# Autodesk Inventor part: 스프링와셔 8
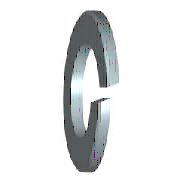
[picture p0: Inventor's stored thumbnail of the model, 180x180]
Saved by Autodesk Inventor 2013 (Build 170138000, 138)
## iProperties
IsCustomPart: 1
Created: 2012-02
Part Number: 스프링와셔 8
Material: 강철, 연강
Description: 스프링 잠금 와셔
Document SubType Name: Modeling
Standard: KS B 1324
Designer: mduedu
Standards Organization: KS
Language: ko-KR
Size Designation: 번호 3 - 8
Categories: <MemberInstance><Categories><Category DisplayName="조임쇠" InternalName="e4da775c-781d-43d5-af7c-5136215cf5a6" Mnemonic="FSTN"><Category DisplayName="와셔" InternalN
Density: 1 g/cm^3
Author: mduedu
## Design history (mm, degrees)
sketch "스케치1"
  geometry: C1 r 7.4 at (0, 0); C2 r 4.1 at (0, 0); 1 further point
  constraints: 2 centre point, 2 coincident
  dimensions: "d0" = 8.2 diameter of C2 (= SD1); "d1" = 14.8 diameter of C1 (= SD2)
extrude "본체" new body sketch "스케치1" distance "d2" = 2.5 (= SD); taper "d3" = 0 deg
sketch "스케치2"
  geometry: L1 (0, -4.1)-(0, 4.1) reference; L2 (2.5, 7.4)-(2.5, -7.4) reference; L3 (-1.2, 0)-(7.2, 0) reference; L4 (0, -0.5)-(2.5, 0.41); L5 (0, 0.5)-(2.5, 1.41)
  constraints: 4 end point, 4 point on line, 1 parallel
  dimensions: "d4" = 0.5 distance from line of L3 L4.start (= 0.2 x SD); "d5" = 0.5 distance from line of L3 L5.start (= 0.2 x SD); "d6" = 70 deg angle of L2 L4 (= FAWI)
extrude "절단부" cut sketch "스케치2" stored distance "d7" = 2.5 (= SD); taper "d8" = 0 deg
workaxis "Work Axis1"
workplane "Work Plane1"
body "Solid1"
other parameters: "SD1" = 8.2 [user parameter; used in 1 equation term], "SD2" = 14.8 [user parameter; used in 1 equation term], "SD" = 2.5 [user parameter; used in 4 equation terms], "FAWI" = 70 deg [user parameter; used in 1 equation term], "d9" = 0, "d10" = 0, "d11" = 0, "d12" = 0, "SDI" = 3.3 [user parameter], "NND" = 8 [user parameter]
